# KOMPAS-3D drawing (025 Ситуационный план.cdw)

Referenced files in D:\Program Files\ASCON\KOMPAS-3D V6 Plus\Templates\: Раб. чертеж зданий и сооружений А1.cdt
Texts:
  ПСПД-0000-2015
  Ситуационный план
  Т1, Ду65
  Узел учета СО
  Т2, Ду65
  Трубопроводы условно отнесены от стен и условно разнесены друг от друга.
  Место установки ШСУ (шкаф связи и управления) узла учета
  уточняется при монтаже.
  Шкаф ШСУ
  Вход в подвал
  Раб. чертеж зданий и сооружений А1.cdt
  Узел учета тепловой энергии,
  теплоносителя
  Пров.
  ЗАО "ПромСервис"
  Разраб.
  ГИП
  ПСПД-0006-2015-
  Рабоч. чертеж зданий и сооруж. ГОСТ Р 21.1101-2009 Ф3.
  Лит-Масса-Масштаб
  Материал-Предприятие
  Стадия
  Лист
  Листов
  Изм.
  Кол.уч.
  №док.
  Подп.
  Дата
  Изменение
  Номер документа
  Подпись
  Обозначение документа
  Наименование предприятия, в состав которого входит здание (сооружение)
  Наименование здания (сооружения)
  Порядковый номер листа
  Количество листов в документе
  Должность подписавшего
  Наименование изображения
  Индекс предприятия, выпускающего документ
  Инв. № подл.
  Подп. и дата
  Взам. инв. №
  Инвентарный номер подлинника
  Подпись принявшего подлинник на хранение
  Инвентарный номер подлинника, взамен которого выпущен данный подлинник
  Согласовано
  Согласование
  Рабоч. чертеж зданий и сооруж. ГОСТ 21.101-97 Ф3.
Dimensions and other numbers on the sheet: 1:1; 1; 22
